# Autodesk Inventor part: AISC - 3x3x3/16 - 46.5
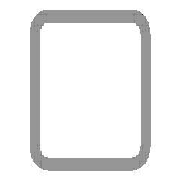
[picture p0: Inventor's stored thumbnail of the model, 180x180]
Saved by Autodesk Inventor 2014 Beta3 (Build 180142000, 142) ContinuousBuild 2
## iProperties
_CCFamilyMember: 9
_CCFamilyDisplayName: ANSI AISC (Square) - Tube
_FrameMemberDoc: Frame Member File
_Version: 15.0.0
_GetPNFromCC: 1
Created: 2011-01
Part Number: AISC - 3x3x3/16 - 46.5
Material: Steel, Mild
Description: Tube
Document SubType Name: Modeling
Standard: ANSI
Designer: Beta-8540w
Standards Organization: ANSI
Language: en-US
Size Designation: 3x3x3/16
Categories: <MemberInstance><Categories><Category DisplayName="Structural Shapes" InternalName="089c4875-fa83-4c05-b084-43b9cc11f5ed" Mnemonic="GRDR"><CategoryParameter Dis
Stock Number: 3x3x3/16
Density: 7.86 g/cm^3
Appearance: Steel
IsCustomPart: 1
G_L: 46.500 in
G_W: 3.000 in
G_H: 3.000 in
Author: Beta-8540w
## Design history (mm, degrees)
node "Start plane"
node "End plane"
sketch "Sketch"
  geometry: L1 (-38.1, -28.575)-(-38.1, 28.575); L2 (-28.575, 38.1)-(28.575, 38.1); L3 (38.1, 28.575)-(38.1, -28.575); L4 (28.575, -38.1)-(-28.575, -38.1); L5 (-28.575, 33.337)-(28.575, 33.338); L6 (33.338, 28.575)-(33.338, -28.575); L7 (28.575, -33.337)-(-28.575, -33.338); L8 (-33.338, -28.575)-(-33.338, 28.575); L9 (0, 56.102)-(0, -56.102) reference; L10 (-56.102, 0)-(56.102, 0) reference; A1 r 9.525 centre (-28.575, -28.575) between (-38.1, -28.575) and (-28.575, -38.1); A2 r 9.525 centre (-28.575, 28.575) between (-28.575, 38.1) and (-38.1, 28.575); A3 r 9.525 centre (28.575, 28.575) between (38.1, 28.575) and (28.575, 38.1); A4 r 9.525 centre (28.575, -28.575) between (28.575, -38.1) and (38.1, -28.575); A5 r 4.763 centre (-28.575, 28.575) between (-28.575, 33.337) and (-33.338, 28.575); A6 r 4.763 centre (28.575, 28.575) between (33.338, 28.575) and (28.575, 33.338); A7 r 4.763 centre (28.575, -28.575) between (28.575, -33.337) and (33.338, -28.575); A8 r 4.763 centre (-28.575, -28.575) between (-33.338, -28.575) and (-28.575, -33.338)
  constraints: 16 end point, 16 point on circle, 8 centre point, 8 tangent, 4 parallel, 3 equal radius, 2 perpendicular, 7 other
  dimensions: "d10" = 76.2 distance between parallel lines of L2 L4 (= G_H); "d11" = 76.2 distance between parallel lines of L1 L3 (= G_W); "d12" = 4.7625 distance between parallel lines of L3 L6 (= G_T); "d15" = 38.1 distance between parallel lines of L2 L10 (= 0.5 x d10); "d16" = 38.1 distance between parallel lines of L9 L3 (= 0.5 x d11); "d17" = 9.525 radius of A1 (= G_IR)
extrude "Body" new body sketch "Sketch" stored distance "d3" = 1181.1 (= G_L); taper "d4" = 0 deg
node "Driven Length"
  sketch "Sketch3"
    geometry: L1 (0, 0)-(10, 0) reference
    constraints: 2 end point, 1 horizontal
  workplane "Work Plane3"
  sketch "Sketch4"
    geometry: L1 (-2, 38.1)-(12, 38.1) reference; L2 (-2, 1219.2)-(12, 1219.2) reference
    dimensions: "d19" = 1181.1 distance between parallel lines of L1 L2 (derived)
workplane "Work Plane4"
split "Split1"
body "Solid1"
other parameters: "G_W" = 76.2 [user parameter; used in 1 equation term], "G_H" = 76.2 [user parameter; used in 1 equation term], "G_T" = 4.7625 [user parameter; used in 1 equation term], "G_IR" = 9.525 [user parameter; used in 1 equation term], "G_L" = 1181.1 (= d19) [user parameter; used in 1 equation term], "G_OFFSET_START" = -38.1 [user parameter; used in 1 equation term], "G_OFFSET_END" = 0 [user parameter; used in 1 equation term], "d13" = 38.1 (= -G_OFFSET_START), "d14" = 1219.2 (= G_OFFSET_END + B_L), "B_L" = 1219.2 [user parameter; used in 1 equation term], "d18" = 90 deg
